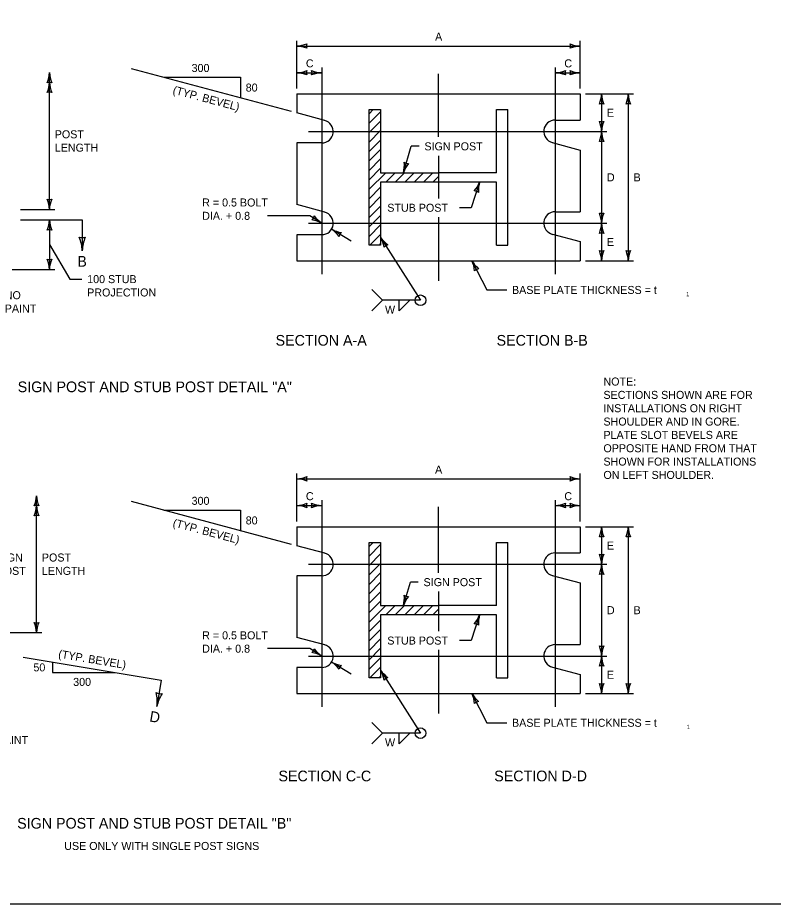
# Model space of a CAD drawing. Extents: x 49991.4 to 50021, y 49987.6 to 50011.4.
# Drawn here: x 50002.29 to 50007.95, y 49987.8 to 49994.44 of the extents above; entities that cross this region are included whole.
import ezdxf

# ---------------------------------------------------------------- set-up
doc = ezdxf.new("R2010")
doc.units = 0
for name, color, linetype in [('Level 1', 7, 'Continuous'), ('Level 2', 7, 'Continuous'), ('Level 3', 7, 'Continuous'), ('Level 5', 7, 'Continuous'), ('Level 6', 7, 'Continuous')]:
    doc.layers.add(name, color=color, linetype=linetype)

msp = doc.modelspace()

# ---------------------------------------------------------------- linework, layer by layer
at = {"layer": 'Level 1'}
for p, q in [((50004.3792, 49993.8723), (50006.5042, 49993.8723)), ((50004.3792, 49993.8723), (50004.3792, 49993.7302)), ((50006.5042, 49993.8723), (50006.5042, 49993.677)), ((50004.9217, 49992.7398), (50004.9217, 49993.7548)), ((50004.9217, 49993.7548), (50005.0079, 49993.7548)), ((50004.9217, 49993.7238), (50004.9527, 49993.7548)), ((50004.9217, 49993.6531), (50005.0079, 49993.7393)), ((50005.0079, 49993.7548), (50005.0079, 49993.2823)), ((50005.8754, 49993.7548), (50005.9617, 49993.7548)), ((50005.8754, 49993.2823), (50005.8754, 49993.7548)), ((50005.9617, 49992.7398), (50005.9617, 49993.7548)), ((50004.5889, 49993.6741), (50004.3792, 49993.7302)), ((50004.9217, 49993.5824), (50005.0079, 49993.6686)), ((50006.3167, 49993.677), (50006.5042, 49993.677)), ((50004.9217, 49993.5117), (50005.0079, 49993.5979)), ((50004.5667, 49993.5051), (50004.3792, 49993.5051)), ((50004.3792, 49993.5051), (50004.3792, 49993.0427)), ((50004.9217, 49993.4409), (50005.0079, 49993.5271)), ((50006.2945, 49993.508), (50006.5042, 49993.452)), ((50004.9217, 49993.3702), (50005.0079, 49993.4564)), ((50006.5042, 49993.452), (50006.5042, 49992.9895)), ((50004.9217, 49993.2995), (50005.0079, 49993.3857)), ((50004.9217, 49993.2288), (50005.0079, 49993.315)), ((50004.9217, 49993.1581), (50005.0459, 49993.2823)), ((50005.0079, 49993.2823), (50005.4417, 49993.2823)), ((50005.0466, 49993.2123), (50005.1166, 49993.2823)), ((50005.1173, 49993.2123), (50005.1873, 49993.2823)), ((50005.188, 49993.2123), (50005.258, 49993.2823)), ((50005.2587, 49993.2123), (50005.3287, 49993.2823)), ((50005.3295, 49993.2123), (50005.3995, 49993.2823)), ((50005.8754, 49993.2823), (50005.4417, 49993.2823)), ((50005.4417, 49993.2823), (50005.4417, 49993.2123)), ((50005.4417, 49993.2123), (50005.0079, 49993.2123)), ((50005.0079, 49993.2123), (50005.0079, 49992.7398)), ((50005.4002, 49993.2123), (50005.4417, 49993.2538)), ((50005.8754, 49993.2123), (50005.4417, 49993.2123)), ((50005.8754, 49992.7398), (50005.8754, 49993.2123)), ((50004.9217, 49993.0874), (50005.0079, 49993.1736)), ((50004.9217, 49993.0167), (50005.0079, 49993.1029)), ((50004.5889, 49992.9866), (50004.3792, 49993.0427)), ((50004.9217, 49992.946), (50005.0079, 49993.0322)), ((50004.9217, 49992.8753), (50005.0079, 49992.9615)), ((50006.3167, 49992.9895), (50006.5042, 49992.9895)), ((50004.9217, 49992.8045), (50005.0079, 49992.8907)), ((50004.5667, 49992.8176), (50004.3792, 49992.8176)), ((50004.3792, 49992.8176), (50004.3792, 49992.6223)), ((50004.9277, 49992.7398), (50005.0079, 49992.82)), ((50006.295, 49992.8204), (50006.5042, 49992.7658)), ((50005.0079, 49992.7398), (50004.9217, 49992.7398)), ((50004.9984, 49992.7398), (50005.0079, 49992.7493)), ((50005.8754, 49992.7398), (50005.9617, 49992.7398)), ((50006.5042, 49992.7658), (50006.5042, 49992.6223)), ((50004.3792, 49992.6223), (50006.5042, 49992.6223)), ((50004.3792, 49990.6281), (50006.5042, 49990.6281)), ((50004.3792, 49990.6281), (50004.3792, 49990.486)), ((50006.5042, 49990.6281), (50006.5042, 49990.4328)), ((50004.5889, 49990.4299), (50004.3792, 49990.486)), ((50004.9217, 49989.4956), (50004.9217, 49990.5106)), ((50004.9217, 49990.5106), (50005.0079, 49990.5106)), ((50004.9217, 49990.4796), (50004.9527, 49990.5106)), ((50004.9217, 49990.4089), (50005.0079, 49990.4951)), ((50005.0079, 49990.5106), (50005.0079, 49990.0381)), ((50005.8754, 49990.5106), (50005.9617, 49990.5106)), ((50005.8754, 49990.0381), (50005.8754, 49990.5106)), ((50005.9617, 49989.4956), (50005.9617, 49990.5106)), ((50004.9217, 49990.3382), (50005.0079, 49990.4244)), ((50006.3167, 49990.4328), (50006.5042, 49990.4328)), ((50004.9217, 49990.2675), (50005.0079, 49990.3537)), ((50004.9217, 49990.1967), (50005.0079, 49990.2829)), ((50004.5667, 49990.2609), (50004.3792, 49990.2609)), ((50004.3792, 49990.2609), (50004.3792, 49989.7985)), ((50004.9217, 49990.126), (50005.0079, 49990.2122)), ((50006.2945, 49990.2638), (50006.5042, 49990.2078)), ((50006.5042, 49990.2078), (50006.5042, 49989.7453)), ((50004.9217, 49990.0553), (50005.0079, 49990.1415)), ((50004.9217, 49989.9846), (50005.0079, 49990.0708)), ((50004.9217, 49989.9139), (50005.0459, 49990.0381)), ((50005.0079, 49990.0381), (50005.4417, 49990.0381)), ((50005.0466, 49989.9681), (50005.1166, 49990.0381)), ((50005.1173, 49989.9681), (50005.1873, 49990.0381)), ((50005.188, 49989.9681), (50005.258, 49990.0381)), ((50005.2587, 49989.9681), (50005.3287, 49990.0381)), ((50005.3295, 49989.9681), (50005.3995, 49990.0381)), ((50005.8754, 49990.0381), (50005.4417, 49990.0381)), ((50005.4417, 49990.0381), (50005.4417, 49989.9681)), ((50005.4417, 49989.9681), (50005.0079, 49989.9681)), ((50005.0079, 49989.9681), (50005.0079, 49989.4956)), ((50005.4002, 49989.9681), (50005.4417, 49990.0096)), ((50005.8754, 49989.9681), (50005.4417, 49989.9681)), ((50005.8754, 49989.4956), (50005.8754, 49989.9681)), ((50004.9217, 49989.8432), (50005.0079, 49989.9294)), ((50004.9217, 49989.7725), (50005.0079, 49989.8587)), ((50004.5889, 49989.7424), (50004.3792, 49989.7985)), ((50004.9217, 49989.7018), (50005.0079, 49989.788)), ((50004.9217, 49989.6311), (50005.0079, 49989.7173)), ((50006.3167, 49989.7453), (50006.5042, 49989.7453)), ((50004.9217, 49989.5603), (50005.0079, 49989.6465)), ((50004.5667, 49989.5734), (50004.3792, 49989.5734)), ((50004.3792, 49989.5734), (50004.3792, 49989.3781)), ((50004.9277, 49989.4956), (50005.0079, 49989.5758)), ((50006.295, 49989.5762), (50006.5042, 49989.5216)), ((50005.0079, 49989.4956), (50004.9217, 49989.4956)), ((50004.9984, 49989.4956), (50005.0079, 49989.5051)), ((50005.8754, 49989.4956), (50005.9617, 49989.4956)), ((50006.5042, 49989.5216), (50006.5042, 49989.3781)), ((50004.3792, 49989.3781), (50006.5042, 49989.3781))]:
    msp.add_line(p, q, dxfattribs=at)
msp.add_lwpolyline([(49999.3835, 49998.9992), (50016.7501, 49998.9992), (50016.7501, 49987.7988), (49999.3835, 49987.7988)], close=True, dxfattribs=at)
for centre, start, end in [((50004.5667, 49993.5911), 270, 75.82227), ((50006.3167, 49993.5911), 90, 255.82227), ((50004.5667, 49992.9036), 270, 75.82227), ((50006.3167, 49992.9036), 90, 256.44074), ((50004.5667, 49990.3469), 270, 75.82227), ((50006.3167, 49990.3469), 90, 255.82227), ((50004.5667, 49989.6594), 270, 75.82227), ((50006.3167, 49989.6594), 90, 256.44074)]:
    msp.add_arc(centre, 0.0859, start, end, dxfattribs=at)
at = {"layer": 'Level 3'}
for p, q in [((50004.3792, 49993.9123), (50004.3792, 49994.2717)), ((50006.5042, 49993.9123), (50006.5042, 49994.2717)), ((50004.3792, 49994.2317), (50006.5042, 49994.2317)), ((50002.5249, 49993.0073), (50002.5249, 49994.0327)), ((50004.3406, 49993.7406), (50003.1389, 49994.0619)), ((50004.3792, 49994.0317), (50004.5667, 49994.0317)), ((50005.4417, 49993.5498), (50005.4417, 49994.0223)), ((50006.3167, 49994.0317), (50006.5042, 49994.0317)), ((50003.3815, 49993.9971), (50003.9563, 49993.9971)), ((50003.9563, 49993.9971), (50003.9563, 49993.8434)), ((50006.5442, 49993.8723), (50006.9042, 49993.8723)), ((50006.6642, 49993.8723), (50006.6642, 49993.5911)), ((50006.8642, 49993.8723), (50006.8642, 49992.6223)), ((50006.6642, 49993.5911), (50006.6642, 49992.9036)), ((50005.1791, 49993.2823), (50005.2374, 49993.4798)), ((50005.2961, 49993.4798), (50005.2374, 49993.4798)), ((50005.4417, 49993.4098), (50005.4417, 49993.0895)), ((50005.7497, 49993.2123), (50005.687, 49993.0195)), ((50002.307, 49993.0073), (50002.5649, 49993.0073)), ((50005.687, 49993.0195), (50005.5994, 49993.0195)), ((50004.4762, 49992.9589), (50004.1604, 49992.9589)), ((50004.5667, 49992.9036), (50004.4762, 49992.9589)), ((50005.4417, 49992.9495), (50005.4417, 49992.4723)), ((50002.5249, 49992.928), (50002.5249, 49992.5575)), ((50006.6642, 49992.9036), (50006.6642, 49992.6223)), ((50004.7881, 49992.7685), (50004.64, 49992.8588)), ((50002.5249, 49992.7428), (50002.6772, 49992.4845)), ((50005.0079, 49992.7969), (50005.3071, 49992.3257)), ((50005.6923, 49992.6223), (50005.805, 49992.4034)), ((50006.5442, 49992.6223), (50006.9042, 49992.6223)), ((50002.2446, 49992.5575), (50002.5649, 49992.5575)), ((50002.6772, 49992.4845), (50002.7679, 49992.4845)), ((50004.9427, 49992.4057), (50005.0227, 49992.3257)), ((50005.805, 49992.4034), (50005.9527, 49992.4034)), ((50004.9427, 49992.2457), (50005.0227, 49992.3257)), ((50005.3071, 49992.3257), (50005.0227, 49992.3257)), ((50005.1471, 49992.2457), (50005.1471, 49992.3257)), ((50005.1471, 49992.2457), (50005.2271, 49992.3257)), ((50005.1472, 49992.3256), (50005.1472, 49992.3256)), ((50004.3792, 49990.6681), (50004.3792, 49991.0275)), ((50006.5042, 49990.6681), (50006.5042, 49991.0275)), ((50004.3792, 49990.9875), (50006.5042, 49990.9875)), ((50002.4283, 49989.8352), (50002.4283, 49990.8606)), ((50004.3406, 49990.4964), (50003.1389, 49990.8177)), ((50003.3815, 49990.7528), (50003.9563, 49990.7528)), ((50003.9563, 49990.7528), (50003.9563, 49990.5991)), ((50004.3792, 49990.7875), (50004.5667, 49990.7875)), ((50005.4417, 49990.2831), (50005.4417, 49990.7781)), ((50006.3167, 49990.7875), (50006.5042, 49990.7875)), ((50006.5442, 49990.6281), (50006.9042, 49990.6281)), ((50006.6642, 49990.6281), (50006.6642, 49990.3469)), ((50006.8642, 49990.6281), (50006.8642, 49989.3781)), ((50006.6642, 49990.3469), (50006.6642, 49989.6594)), ((50005.1791, 49990.0381), (50005.2308, 49990.2131)), ((50005.2895, 49990.2131), (50005.2308, 49990.2131)), ((50005.4417, 49990.1431), (50005.4417, 49989.8453)), ((50005.7497, 49989.9681), (50005.687, 49989.7753)), ((50001.7296, 49989.8352), (50002.4683, 49989.8352)), ((50005.687, 49989.7753), (50005.5994, 49989.7753)), ((50004.4762, 49989.7147), (50004.1604, 49989.7147)), ((50004.5667, 49989.6594), (50004.4762, 49989.7147)), ((50005.4417, 49989.7053), (50005.4417, 49989.2281)), ((50002.5472, 49989.6135), (50002.5472, 49989.5355)), ((50004.788, 49989.5242), (50004.64, 49989.6146)), ((50006.6642, 49989.6594), (50006.6642, 49989.3781)), ((50005.0079, 49989.5527), (50005.3071, 49989.0815)), ((50002.5472, 49989.5355), (50003.0153, 49989.5355)), ((50005.6923, 49989.3781), (50005.805, 49989.1592)), ((50006.5442, 49989.3781), (50006.9042, 49989.3781)), ((50004.9427, 49989.1615), (50005.0227, 49989.0815)), ((50005.805, 49989.1592), (50005.9527, 49989.1592)), ((50004.9427, 49989.0015), (50005.0227, 49989.0815)), ((50005.3071, 49989.0815), (50005.0227, 49989.0815)), ((50005.1471, 49989.0015), (50005.1471, 49989.0815)), ((50005.1471, 49989.0015), (50005.2271, 49989.0815))]:
    msp.add_line(p, q, dxfattribs=at)
for centre in [(50005.3071, 49992.3257), (50005.3071, 49989.0815)]:
    msp.add_circle(centre, 0.04, dxfattribs=at)
for centre, radius, start, end in [((50004.3677, 49994.4644), 0.233, 272.82731, 292.07716), ((50004.37, 49994.0096), 0.2223, 67.45601, 87.63952), ((50004.5074, 49994.2317), 0.0548, 162.13882, 197.86118), ((50006.5134, 49994.4538), 0.2223, 247.45601, 267.63952), ((50006.376, 49994.2317), 0.0548, 342.13882, 17.86118), ((50006.5157, 49993.999), 0.233, 92.82731, 112.07716), ((50002.3028, 49994.0419), 0.2223, 337.45601, 357.63952), ((50002.7576, 49994.0442), 0.233, 182.82731, 202.07716), ((50004.3677, 49994.2644), 0.233, 272.82731, 292.07716), ((50004.37, 49993.8096), 0.2223, 67.45601, 87.63952), ((50004.5074, 49994.0317), 0.0548, 162.13882, 197.86118), ((50004.5759, 49994.2538), 0.2223, 247.45601, 267.63952), ((50004.4385, 49994.0317), 0.0548, 342.13882, 17.86118), ((50004.5782, 49993.799), 0.233, 92.82731, 112.07716), ((50006.3052, 49994.2644), 0.233, 272.82731, 292.07716), ((50006.3075, 49993.8096), 0.2223, 67.45601, 87.63952), ((50006.4449, 49994.0317), 0.0548, 162.13882, 197.86118), ((50006.5134, 49994.2538), 0.2223, 247.45601, 267.63952), ((50006.376, 49994.0317), 0.0548, 342.13882, 17.86118), ((50006.5157, 49993.799), 0.233, 92.82731, 112.07716), ((50002.3028, 49993.9684), 0.2223, 337.45601, 357.63952), ((50002.5249, 49993.9045), 0.0548, 72.13882, 107.86118), ((50002.7576, 49993.9708), 0.233, 182.82731, 202.07716), ((50002.5249, 49993.831), 0.0548, 72.13882, 107.86118), ((50006.4421, 49993.8815), 0.2223, 337.45601, 357.63952), ((50006.8969, 49993.8838), 0.233, 182.82731, 202.07716), ((50006.6421, 49993.8815), 0.2223, 337.45601, 357.63952), ((50007.0969, 49993.8838), 0.233, 182.82731, 202.07716), ((50006.6642, 49993.7441), 0.0548, 72.13882, 107.86118), ((50006.8642, 49993.7441), 0.0548, 72.13882, 107.86118), ((50006.6642, 49993.7193), 0.0548, 252.13882, 287.86118), ((50006.4315, 49993.5796), 0.233, 2.82731, 22.07716), ((50006.8863, 49993.5819), 0.2223, 157.45601, 177.63952), ((50006.4421, 49993.6003), 0.2223, 337.45601, 357.63952), ((50006.8969, 49993.6026), 0.233, 182.82731, 202.07716), ((50006.6642, 49993.4629), 0.0548, 72.13882, 107.86118), ((50004.9527, 49993.3372), 0.233, 346.37226, 5.62211), ((50005.3895, 49993.2106), 0.2223, 141.00096, 161.18447), ((50005.2154, 49993.4053), 0.0548, 235.68377, 271.40613), ((50005.5412, 49993.2897), 0.2223, 319.44905, 339.63256), ((50005.9745, 49993.1513), 0.233, 164.82035, 184.0702), ((50005.71, 49993.0904), 0.0548, 54.13186, 89.85422), ((50002.5249, 49993.1355), 0.0548, 252.13882, 287.86118), ((50002.2922, 49992.9958), 0.233, 2.82731, 22.07716), ((50002.747, 49992.9981), 0.2223, 157.45601, 177.63952), ((50004.4573, 49992.9705), 0.0548, 310.71181, 346.43418), ((50004.6903, 49993.0884), 0.2223, 216.02901, 236.21251), ((50006.6642, 49993.0318), 0.0548, 252.13882, 287.86118), ((50006.4315, 49992.8921), 0.233, 2.82731, 22.07716), ((50006.8863, 49992.8944), 0.2223, 157.45601, 177.63952), ((50002.3028, 49992.9372), 0.2223, 337.45601, 357.63952), ((50002.7576, 49992.9395), 0.233, 182.82731, 202.07716), ((50004.4552, 49992.699), 0.233, 61.40031, 80.65016), ((50006.4421, 49992.9128), 0.2223, 337.45601, 357.63952), ((50006.8969, 49992.9151), 0.233, 182.82731, 202.07716), ((50002.5249, 49992.7998), 0.0548, 72.13882, 107.86118), ((50004.5165, 49992.6739), 0.2223, 36.06348, 56.24699), ((50004.7514, 49993.0634), 0.233, 241.43478, 260.68463), ((50004.7495, 49992.792), 0.0548, 130.74629, 166.46865), ((50006.6642, 49992.7754), 0.0548, 72.13882, 107.86118), ((50004.8155, 49992.6855), 0.2223, 9.8716, 30.05511), ((50005.1982, 49992.9313), 0.233, 215.2429, 234.49275), ((50005.0766, 49992.6886), 0.0548, 104.55441, 140.27677), ((50006.6642, 49992.7505), 0.0548, 252.13882, 287.86118), ((50006.4315, 49992.6108), 0.233, 2.82731, 22.07716), ((50006.8863, 49992.6131), 0.2223, 157.45601, 177.63952), ((50006.8642, 49992.7505), 0.0548, 252.13882, 287.86118), ((50006.6315, 49992.6108), 0.233, 2.82731, 22.07716), ((50007.0863, 49992.6131), 0.2223, 157.45601, 177.63952), ((50002.5249, 49992.6857), 0.0548, 252.13882, 287.86118), ((50002.2922, 49992.546), 0.233, 2.82731, 22.07716), ((50002.747, 49992.5483), 0.2223, 157.45601, 177.63952), ((50005.4906, 49992.5288), 0.2223, 4.69755, 24.88106), ((50005.8939, 49992.739), 0.233, 210.06885, 229.3187), ((50005.751, 49992.5083), 0.0548, 99.38036, 135.10272), ((50004.3677, 49991.2202), 0.233, 272.82731, 292.07716), ((50004.37, 49990.7654), 0.2223, 67.45601, 87.63952), ((50004.5074, 49990.9875), 0.0548, 162.13882, 197.86118), ((50006.5134, 49991.2096), 0.2223, 247.45601, 267.63952), ((50006.376, 49990.9875), 0.0548, 342.13882, 17.86118), ((50006.5157, 49990.7548), 0.233, 92.82731, 112.07716), ((50002.2062, 49990.8698), 0.2223, 337.45601, 357.63952), ((50002.661, 49990.8721), 0.233, 182.82731, 202.07716), ((50002.2062, 49990.7963), 0.2223, 337.45601, 357.63952), ((50002.4283, 49990.7324), 0.0548, 72.13882, 107.86118), ((50002.661, 49990.7987), 0.233, 182.82731, 202.07716), ((50004.3677, 49991.0202), 0.233, 272.82731, 292.07716), ((50004.37, 49990.5654), 0.2223, 67.45601, 87.63952), ((50004.5074, 49990.7875), 0.0548, 162.13882, 197.86118), ((50004.5759, 49991.0096), 0.2223, 247.45601, 267.63952), ((50004.4385, 49990.7875), 0.0548, 342.13882, 17.86118), ((50004.5782, 49990.5548), 0.233, 92.82731, 112.07716), ((50006.3052, 49991.0202), 0.233, 272.82731, 292.07716), ((50006.3075, 49990.5654), 0.2223, 67.45601, 87.63952), ((50006.4449, 49990.7875), 0.0548, 162.13882, 197.86118), ((50006.5134, 49991.0096), 0.2223, 247.45601, 267.63952), ((50006.376, 49990.7875), 0.0548, 342.13882, 17.86118), ((50006.5157, 49990.5548), 0.233, 92.82731, 112.07716), ((50002.4283, 49990.6589), 0.0548, 72.13882, 107.86118), ((50006.4421, 49990.6373), 0.2223, 337.45601, 357.63952), ((50006.8969, 49990.6396), 0.233, 182.82731, 202.07716), ((50006.6421, 49990.6373), 0.2223, 337.45601, 357.63952), ((50007.0969, 49990.6396), 0.233, 182.82731, 202.07716), ((50006.6642, 49990.4999), 0.0548, 72.13882, 107.86118), ((50006.8642, 49990.4999), 0.0548, 72.13882, 107.86118), ((50006.6642, 49990.4751), 0.0548, 252.13882, 287.86118), ((50006.4315, 49990.3354), 0.233, 2.82731, 22.07716), ((50006.8863, 49990.3377), 0.2223, 157.45601, 177.63952), ((50006.4421, 49990.3561), 0.2223, 337.45601, 357.63952), ((50006.8969, 49990.3584), 0.233, 182.82731, 202.07716), ((50006.6642, 49990.2187), 0.0548, 72.13882, 107.86118), ((50004.9527, 49990.093), 0.233, 346.37226, 5.62211), ((50005.3895, 49989.9664), 0.2223, 141.00096, 161.18447), ((50005.2154, 49990.1611), 0.0548, 235.68377, 271.40613), ((50005.5412, 49990.0455), 0.2223, 319.44905, 339.63256), ((50005.9745, 49989.9071), 0.233, 164.82035, 184.0702), ((50002.4283, 49989.9634), 0.0548, 252.13882, 287.86118), ((50002.1956, 49989.8237), 0.233, 2.82731, 22.07716), ((50002.6504, 49989.826), 0.2223, 157.45601, 177.63952), ((50005.71, 49989.8462), 0.0548, 54.13186, 89.85422), ((50004.4573, 49989.7263), 0.0548, 310.71181, 346.43418), ((50004.4552, 49989.4548), 0.233, 61.40031, 80.65016), ((50004.6903, 49989.8442), 0.2223, 216.02901, 236.21251), ((50006.6642, 49989.7876), 0.0548, 252.13882, 287.86118), ((50006.4315, 49989.6479), 0.233, 2.82731, 22.07716), ((50006.8863, 49989.6502), 0.2223, 157.45601, 177.63952), ((50004.5165, 49989.4297), 0.2223, 36.06348, 56.24699), ((50004.7514, 49989.8192), 0.233, 241.43478, 260.68463), ((50006.4421, 49989.6686), 0.2223, 337.45601, 357.63952), ((50006.8969, 49989.6709), 0.233, 182.82731, 202.07716), ((50004.7495, 49989.5478), 0.0548, 130.74629, 166.46865), ((50004.8155, 49989.4413), 0.2223, 9.8716, 30.05511), ((50005.1982, 49989.6871), 0.233, 215.2429, 234.49275), ((50006.6642, 49989.5312), 0.0548, 72.13882, 107.86118), ((50005.0766, 49989.4444), 0.0548, 104.55441, 140.27677), ((50006.6642, 49989.5063), 0.0548, 252.13882, 287.86118), ((50006.4315, 49989.3666), 0.233, 2.82731, 22.07716), ((50006.8863, 49989.3689), 0.2223, 157.45601, 177.63952), ((50006.8642, 49989.5063), 0.0548, 252.13882, 287.86118), ((50006.6315, 49989.3666), 0.233, 2.82731, 22.07716), ((50007.0863, 49989.3689), 0.2223, 157.45601, 177.63952), ((50005.4906, 49989.2846), 0.2223, 4.69755, 24.88106), ((50005.8939, 49989.4948), 0.233, 210.06885, 229.3187), ((50005.751, 49989.2641), 0.0548, 99.38036, 135.10272)]:
    msp.add_arc(centre, radius, start, end, dxfattribs=at)
at = {"layer": 'Level 5'}
for p, q in [((50004.5667, 49994.0717), (50004.5667, 49992.5223)), ((50006.3167, 49994.0717), (50006.3167, 49992.5223)), ((50004.4667, 49993.5911), (50006.7042, 49993.5911)), ((50004.4667, 49992.9036), (50006.7042, 49992.9036)), ((50004.5667, 49990.8275), (50004.5667, 49989.2781)), ((50006.3167, 49990.8275), (50006.3167, 49989.2781)), ((50004.4667, 49990.3469), (50006.7042, 49990.3469)), ((50004.4667, 49989.6594), (50006.7042, 49989.6594))]:
    msp.add_line(p, q, dxfattribs=at)
at = {"layer": 'Level 6'}
for p, q in [((50002.307, 49992.928), (50002.7711, 49992.928)), ((50002.7711, 49992.928), (50002.7711, 49992.6977)), ((50002.3274, 49989.6502), (50003.3633, 49989.4775)), ((50003.3633, 49989.4775), (50003.3306, 49989.2813))]:
    msp.add_line(p, q, dxfattribs=at)
for centre, radius, start, end in [((50002.7711, 49992.8687), 0.073, 252.13882, 287.86118), ((50002.4608, 49992.6824), 0.3107, 2.82731, 22.07716), ((50003.0673, 49992.6855), 0.2964, 157.45601, 177.63952), ((50003.3587, 49989.4499), 0.073, 242.6765, 278.39886), ((50003.022, 49989.3172), 0.3107, 353.36499, 12.61484), ((50003.6207, 49989.2206), 0.2964, 147.99369, 168.1772)]:
    msp.add_arc(centre, radius, start, end, dxfattribs=at)

# ---------------------------------------------------------------- texts
at = {"layer": 'Level 2'}
for s, height, p in [('A', 0.06, (50005.416, 49994.2717)), ('C', 0.06, (50004.4475, 49994.0717)), ('C', 0.06, (50006.3849, 49994.0717)), ('300', 0.06, (50003.5907, 49994.0371)), ('80', 0.06, (50003.9963, 49993.8902)), ('E', 0.06, (50006.7042, 49993.7017)), ('POST', 0.06, (50002.5649, 49993.54)), ('LENGTH', 0.06, (50002.5649, 49993.44)), ('SIGN POST', 0.06, (50005.3361, 49993.4498)), ('D', 0.06, (50006.7042, 49993.2174)), ('B', 0.06, (50006.9042, 49993.2173)), ('R = 0.5 BOLT', 0.06, (50003.6699, 49993.0289)), ('STUB POST', 0.06, (50005.0577, 49992.9895)), ('DIA. + 0.8', 0.06, (50003.6699, 49992.9289)), ('E', 0.06, (50006.7042, 49992.733)), ('B', 0.08, (50002.7341, 49992.5777)), ('100 STUB', 0.06, (50002.8079, 49992.4545)), ('PROJECTION', 0.06, (50002.8079, 49992.3545)), ('BASE PLATE THICKNESS = t', 0.06, (50005.9927, 49992.3734)), ('NO', 0.06, (50002.1901, 49992.334)), ('1', 0.0325, (50007.2978, 49992.3561)), ('PAINT', 0.06, (50002.1901, 49992.234)), ('W', 0.06, (50005.0406, 49992.2257)), ('SECTION A-A', 0.08, (50004.2205, 49991.9858)), ('SECTION B-B', 0.08, (50005.8773, 49991.9858)), ('NOTE:', 0.06, (50006.6781, 49991.6868)), ('SIGN POST AND STUB POST DETAIL "A"', 0.08, (50002.2869, 49991.6371)), ('SECTIONS SHOWN ARE FOR', 0.06, (50006.6781, 49991.5868)), ('INSTALLATIONS ON RIGHT', 0.06, (50006.6781, 49991.4868)), ('SHOULDER AND IN GORE.', 0.06, (50006.6781, 49991.3868)), ('PLATE SLOT BEVELS ARE', 0.06, (50006.6781, 49991.2868)), ('OPPOSITE HAND FROM THAT', 0.06, (50006.6781, 49991.1868)), ('SHOWN FOR INSTALLATIONS', 0.06, (50006.6781, 49991.0868)), ('A', 0.06, (50005.416, 49991.0275)), ('ON LEFT SHOULDER.', 0.06, (50006.6781, 49990.9868)), ('C', 0.06, (50004.4475, 49990.8275)), ('C', 0.06, (50006.3849, 49990.8275)), ('300', 0.06, (50003.5907, 49990.7928)), ('80', 0.06, (50003.9963, 49990.6459)), ('E', 0.06, (50006.7042, 49990.4575)), ('SIGN', 0.06, (50002.129, 49990.3679)), ('POST', 0.06, (50002.4683, 49990.3679)), ('POST', 0.06, (50002.129, 49990.2679)), ('LENGTH', 0.06, (50002.4683, 49990.2679)), ('SIGN POST', 0.06, (50005.3295, 49990.1831)), ('D', 0.06, (50006.7042, 49989.9732)), ('B', 0.06, (50006.9042, 49989.9731)), ('R = 0.5 BOLT', 0.06, (50003.6699, 49989.7847)), ('STUB POST', 0.06, (50005.0577, 49989.7453)), ('DIA. + 0.8', 0.06, (50003.6699, 49989.6847)), ('50', 0.06, (50002.4048, 49989.5445)), ('E', 0.06, (50006.7042, 49989.4888)), ('300', 0.06, (50002.703, 49989.4355)), ('BASE PLATE THICKNESS = t', 0.06, (50005.9927, 49989.1292)), ('1', 0.0325, (50007.3028, 49989.1119)), ('PAINT', 0.06, (50002.129, 49989.0004)), ('W', 0.06, (50005.0406, 49988.9815)), ('SECTION C-C', 0.08, (50004.2418, 49988.7204)), ('SECTION D-D', 0.08, (50005.8593, 49988.7204)), ('SIGN POST AND STUB POST DETAIL "B"', 0.08, (50002.2831, 49988.3659)), ('USE ONLY WITH SINGLE POST SIGNS', 0.06, (50002.6359, 49988.2059))]:
    msp.add_text(s, height=height, dxfattribs=at).set_placement(p)
for s, height, rotation, p in [('(TYP. BEVEL)', 0.06, 345.023, (50003.4455, 49993.8764)), ('(TYP. BEVEL)', 0.06, 345.023, (50003.4455, 49990.6322)), ('(TYP. BEVEL)', 0.059999, 350.539, (50002.5881, 49989.6472)), ('D', 0.08, 350.55, (50003.271, 49989.1696))]:
    msp.add_text(s, height=height, rotation=rotation, dxfattribs=at).set_placement(p)

doc.saveas('drawing.dxf')
